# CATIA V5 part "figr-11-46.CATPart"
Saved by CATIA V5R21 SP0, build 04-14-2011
Part number: Part2
Bounding box of the stored display mesh (mm): x 0 to 0, y -71.701 to 140, z -97.468 to 20
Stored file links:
  D:\CATIA V5R21 E-RESOURCES\CATIA-V5R21\catia-v5r21-prt\c11-catia-v5r21-prt\c11-catia-v5r21-figr-11-46.CATPart
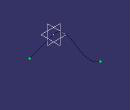
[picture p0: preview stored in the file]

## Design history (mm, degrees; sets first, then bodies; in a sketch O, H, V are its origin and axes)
Set1
  Extrapol1: ToExtrapol Sketch1.O, Support Sketch1, Length 121
Body1 (main body)
  Sketch1 on yz-plane, origin (0, 0, 0), H (0, 1, 0), V (0, 0, 1)
    spline S1 through (0, 0) (30, 20) (100, -10) (140, 0)
    point P1 (0, 0)
    coincidence: P1 O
